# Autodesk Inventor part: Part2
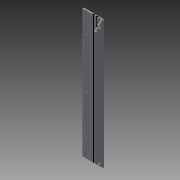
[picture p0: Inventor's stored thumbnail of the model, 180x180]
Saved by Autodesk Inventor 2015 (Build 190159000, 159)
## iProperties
Created: 2018-03
Part Number: Part2
Material: Generic
Document SubType Name: Modeling
Designer: maxzh
Density: 1 g/cm^3
Appearance: Default
Author: maxzh
Title: C:\Users\maxzh\Desktop\USBP\03.01.2018\STEP\Part2.stp
Creation Date: 2018-03-01
Sending System: Autodesk Inventor 2015
Preprocessor: ST-DEVELOPER v15.6
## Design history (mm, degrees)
node "Part21"
body "Solid1"
node "Solid1_1"
node "Solid1_2"
body "Solid2"
node "Solid2_1"
node "Base1"
node "Base2"
node "Base3"
node "Base4"
node "Base5"
